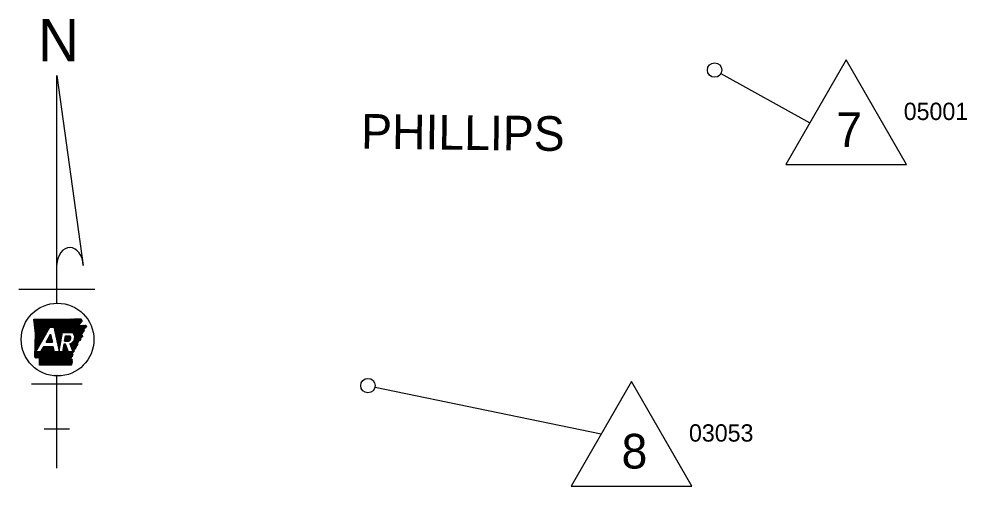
# Model space of a CAD drawing. Extents: x -31696 to 27919, y -8775 to 11152.
# Drawn here: x 10155 to 16721, y -2119 to 1115 of the extents above; entities that cross this region are included whole.
import ezdxf

# ---------------------------------------------------------------- set-up
doc = ezdxf.new("R2010")
doc.units = 0
for name, color, linetype in [('Level 2', 7, 'Continuous'), ('Level 48', 7, 'Continuous'), ('Level 50', 7, 'Continuous')]:
    doc.layers.add(name, color=color, linetype=linetype)

msp = doc.modelspace()

# ---------------------------------------------------------------- linework, layer by layer
at = {"layer": 'Level 48'}
for p, q in [((15883.2, 831.6), (15465.3, 107.7)), ((16301.2, 107.7), (15883.2, 831.6)), ((10418.4, 722.8), (10600.2, -591.3)), ((10418.4, -853), (10418.4, 722.8)), ((15016.1, 736.9), (15631.2, 395.8)), ((15465.3, 107.7), (16301.2, 107.7)), ((10155.2, -755.6), (10681.5, -755.6)), ((10258.7, -965.9), (10260.9, -963.7)), ((10259.5, -972.1), (10267.8, -963.7)), ((10260.3, -978.3), (10274.8, -963.7)), ((10261, -984.5), (10281.8, -963.8)), ((10261.8, -990.7), (10288.7, -963.8)), ((10262.6, -996.9), (10295.7, -963.8)), ((10263.3, -1003.1), (10302.6, -963.8)), ((10264.1, -1009.3), (10309.6, -963.8)), ((10264.9, -1015.5), (10316.6, -963.8)), ((10265.7, -1021.7), (10323.5, -963.8)), ((10266.4, -1027.9), (10330.5, -963.8)), ((10267.2, -1034), (10337.5, -963.8)), ((10268, -1040.2), (10344.4, -963.8)), ((10268.7, -1046.4), (10351.4, -963.8)), ((10269, -1115.9), (10421.2, -963.7)), ((10269.2, -1108.7), (10414.2, -963.7)), ((10269.4, -1101.5), (10407.2, -963.7)), ((10269.5, -1052.6), (10358.4, -963.8)), ((10269.7, -1094.2), (10400.2, -963.7)), ((10269.9, -1087), (10393.3, -963.7)), ((10270.2, -1079.8), (10386.3, -963.7)), ((10270.3, -1058.8), (10365.3, -963.8)), ((10270.4, -1072.6), (10379.3, -963.7)), ((10270.6, -1065.4), (10372.3, -963.8)), ((10372.4, -1019.4), (10428.2, -963.6)), ((10379.4, -1019.4), (10435.1, -963.6)), ((10386.3, -1019.4), (10442.2, -963.6)), ((10393.3, -1019.4), (10449.2, -963.5)), ((10397.6, -1022), (10456.3, -963.3)), ((10398.9, -1027.8), (10463.4, -963.2)), ((10400.1, -1033.5), (10470.5, -963.1)), ((10401.3, -1039.2), (10477.5, -963)), ((10402.6, -1045), (10484.6, -962.9)), ((10403.8, -1050.7), (10491.7, -962.8)), ((10405, -1056.4), (10498.8, -962.7)), ((10406.2, -1062.2), (10505.8, -962.6)), ((10407.5, -1067.9), (10512.9, -962.5)), ((10408.7, -1073.7), (10520, -962.4)), ((10409.9, -1079.4), (10527.1, -962.3)), ((10411.2, -1085.1), (10534.1, -962.1)), ((10412.4, -1090.9), (10541.2, -962)), ((10413.6, -1096.6), (10548.4, -961.8)), ((10462, -1055.2), (10555.5, -961.7)), ((10469, -1055.2), (10562.6, -961.5)), ((10475.9, -1055.2), (10569.8, -961.3)), ((10482.9, -1055.2), (10576.9, -961.2)), ((10489.9, -1055.2), (10584, -961)), ((10496.8, -1055.2), (10585.6, -966.4)), ((10503.8, -1055.2), (10588.9, -970)), ((10510.8, -1055.2), (10589.8, -976.1)), ((10268.5, -1130.3), (10353.6, -1045.1)), ((10268.7, -1123.1), (10362.7, -1029.1)), ((10271, -1191), (10368.2, -1019.4)), ((10368.2, -1019.4), (10397.1, -1019.4)), ((10517.7, -1055.2), (10573.9, -999)), ((10524.1, -1055.8), (10572.6, -1007.3)), ((10527.9, -1059), (10579.9, -1006.9)), ((10531.3, -1062.5), (10587.3, -1006.5)), ((10534.3, -1066.5), (10594.6, -1006.2)), ((10536.9, -1070.9), (10601.9, -1005.8)), ((10539, -1075.7), (10609.3, -1005.4)), ((10540.1, -1102.5), (10603.3, -1039.2)), ((10540.6, -1081.1), (10615.9, -1005.8)), ((10541.5, -1087.1), (10619.2, -1009.5)), ((10541.6, -1094), (10602.5, -1033.1)), ((10595.5, -1054), (10604.1, -1045.4)), ((10616.1, -1019.5), (10622.4, -1013.2)), ((10267.5, -1159.1), (10317.3, -1109.4)), ((10267.8, -1151.9), (10326.4, -1093.3)), ((10268, -1144.7), (10335.4, -1077.3)), ((10268.3, -1137.5), (10344.5, -1061.2)), ((10342.5, -1123.6), (10374.3, -1067.5)), ((10342.9, -1123.6), (10378.7, -1087.8)), ((10349.8, -1123.6), (10379.9, -1093.6)), ((10351.2, -1108.4), (10377.4, -1082.1)), ((10356.8, -1123.6), (10381.1, -1099.3)), ((10360.3, -1092.3), (10376.2, -1076.4)), ((10363.8, -1123.6), (10382.3, -1105.1)), ((10369.4, -1076.2), (10375, -1070.6)), ((10370.7, -1123.6), (10383.6, -1110.8)), ((10414.8, -1102.3), (10454.4, -1062.8)), ((10416.1, -1108.1), (10452.9, -1071.3)), ((10417.3, -1113.8), (10451.4, -1079.7)), ((10418.5, -1119.6), (10450, -1088.1)), ((10419.7, -1125.3), (10448.5, -1096.6)), ((10421, -1131), (10447, -1105)), ((10422.2, -1136.8), (10445.5, -1113.4)), ((10455.7, -1055.2), (10523.2, -1055.2)), ((10470.3, -1116), (10499.3, -1116)), ((10470.4, -1116), (10507, -1079.4)), ((10471.8, -1107.7), (10500.1, -1079.4)), ((10473.3, -1099.2), (10493.1, -1079.4)), ((10474.7, -1090.8), (10486.1, -1079.4)), ((10476.2, -1082.4), (10479.2, -1079.4)), ((10476.7, -1079.4), (10508.4, -1079.4)), ((10477.3, -1116), (10510.9, -1082.5)), ((10484.3, -1116), (10513.3, -1087.1)), ((10491.3, -1116), (10514.5, -1092.8)), ((10498.2, -1116), (10514, -1100.3)), ((10511.4, -1145.1), (10588.6, -1067.9)), ((10513.2, -1150.2), (10589.9, -1073.6)), ((10515.1, -1155.3), (10591.2, -1079.2)), ((10517, -1160.4), (10592.5, -1084.9)), ((10534.1, -1115.5), (10587.3, -1062.3)), ((10568.7, -1115.7), (10578.4, -1105.9)), ((10266.6, -1187.9), (10280.9, -1173.6)), ((10266.8, -1180.7), (10290, -1157.5)), ((10267.1, -1173.5), (10299.1, -1141.5)), ((10267.3, -1166.3), (10308.2, -1125.4)), ((10268.1, -1228.2), (10341.3, -1155)), ((10272.2, -1231), (10348.3, -1155)), ((10277.2, -1233), (10355.2, -1155)), ((10285.5, -1231.7), (10362.2, -1155)), ((10292.6, -1231.6), (10369.2, -1155)), ((10298, -1233.1), (10376.1, -1155)), ((10298.3, -1246.8), (10390.1, -1155)), ((10298.3, -1239.8), (10383.1, -1155)), ((10298.3, -1253.7), (10393.7, -1158.3)), ((10298.3, -1260.6), (10395, -1164)), ((10298.3, -1267.6), (10396.2, -1169.8)), ((10298.4, -1274.5), (10397.4, -1175.5)), ((10298.5, -1281.4), (10398.6, -1181.2)), ((10324.8, -1155), (10304.4, -1191)), ((10312.3, -1177), (10334.3, -1155)), ((10321.4, -1161), (10327.4, -1155)), ((10393, -1155), (10324.8, -1155)), ((10342.5, -1123.6), (10386.3, -1123.6)), ((10368, -1281.5), (10487.8, -1161.7)), ((10375, -1281.5), (10489.7, -1166.8)), ((10377.7, -1123.6), (10384.8, -1116.5)), ((10381.9, -1281.5), (10491.6, -1171.9)), ((10384.7, -1123.6), (10386, -1122.3)), ((10388.9, -1281.5), (10493.5, -1177)), ((10423.4, -1142.5), (10444.1, -1121.9)), ((10424.7, -1148.2), (10442.6, -1130.3)), ((10425.9, -1154), (10441.1, -1138.7)), ((10427.1, -1159.7), (10439.7, -1147.2)), ((10428.3, -1165.5), (10438.2, -1155.6)), ((10429.6, -1171.2), (10436.7, -1164)), ((10430.8, -1176.9), (10435.3, -1172.5)), ((10432, -1182.7), (10433.8, -1180.9)), ((10458.5, -1184.1), (10485.9, -1156.6)), ((10460, -1175.6), (10484.1, -1151.5)), ((10461.4, -1167.2), (10482.2, -1146.4)), ((10462.9, -1158.8), (10480.3, -1141.4)), ((10464.4, -1150.3), (10478.3, -1136.4)), ((10465.8, -1141.9), (10471.3, -1136.4)), ((10478.5, -1136.4), (10466.8, -1136.4)), ((10498.6, -1191), (10478.5, -1136.4)), ((10507, -1133.5), (10528.3, -1191)), ((10507.6, -1135), (10509.7, -1132.9)), ((10509.5, -1140.1), (10522.7, -1126.8)), ((10518.9, -1165.5), (10560.7, -1123.7)), ((10520.7, -1170.6), (10559.9, -1131.5)), ((10522.6, -1175.7), (10559.1, -1139.2)), ((10524.5, -1180.7), (10545.9, -1159.4)), ((10526.4, -1185.8), (10542.9, -1169.3)), ((10265.5, -1223.8), (10298.3, -1191)), ((10265.6, -1216.7), (10291.4, -1191)), ((10265.9, -1209.5), (10284.4, -1191)), ((10266.1, -1202.3), (10277.4, -1191)), ((10266.3, -1195.1), (10271.8, -1189.7)), ((10304.4, -1191), (10271, -1191)), ((10305.4, -1281.4), (10399.9, -1187)), ((10312.4, -1281.4), (10402.8, -1191)), ((10319.3, -1281.4), (10409.8, -1191)), ((10326.3, -1281.4), (10416.7, -1191)), ((10333.2, -1281.5), (10423.7, -1191)), ((10340.2, -1281.5), (10430.7, -1191)), ((10347.2, -1281.5), (10437.6, -1191)), ((10354.1, -1281.5), (10444.6, -1191)), ((10361.1, -1281.5), (10451.6, -1191)), ((10395.8, -1281.6), (10495.3, -1182)), ((10457.3, -1191), (10400.7, -1191)), ((10402.8, -1281.6), (10497.2, -1187.1)), ((10409.7, -1281.6), (10500.3, -1191)), ((10416.7, -1281.6), (10507.3, -1191)), ((10423.7, -1281.6), (10514.3, -1191)), ((10430.6, -1281.6), (10521.2, -1191)), ((10437.6, -1281.6), (10523.6, -1195.6)), ((10444.5, -1281.6), (10523.9, -1202.3)), ((10451.5, -1281.6), (10524.2, -1208.9)), ((10458.4, -1281.7), (10524.5, -1215.6)), ((10465.4, -1281.7), (10513.1, -1234)), ((10472.3, -1281.7), (10515.2, -1238.8)), ((10479.3, -1281.7), (10517.4, -1243.6)), ((10528.3, -1191), (10498.6, -1191)), ((10486.2, -1281.7), (10519.5, -1248.4)), ((10493.2, -1281.7), (10521.7, -1253.3)), ((10500.2, -1281.7), (10523.5, -1258.4)), ((10507.1, -1281.7), (10520.3, -1268.5)), ((10514.1, -1281.7), (10517.2, -1278.7)), ((10418.4, -1996.7), (10418.4, -1357.1)), ((10242.9, -1411.5), (10593.8, -1411.5)), ((12620.8, -1434.1), (14187.2, -1757.4)), ((14396.1, -1395.5), (13978.2, -2119.4)), ((14814.1, -2119.4), (14396.1, -1395.5)), ((10330.6, -1723.1), (10506.1, -1723.1)), ((13978.2, -2119.4), (14814.1, -2119.4))]:
    msp.add_line(p, q, dxfattribs=at)
for points in [[(10258.4, -963.8), (10354.5, -963.8), (10438.9, -963.6), (10538.4, -962.1), (10584.5, -961)], [(10258.4, -963.7), (10354.5, -963.8), (10438.9, -963.6), (10538.4, -962.1), (10584.5, -961)], [(10265.4, -1223.7), (10270.7, -1062.5), (10258.4, -963.7)], [(10269.1, -1113.1), (10270.7, -1062.5), (10258.4, -963.8)], [(10397.1, -1019.4), (10432.8, -1186.4), (10455.7, -1055.2)], [(10614.7, -1005.2), (10623, -1013.8), (10602.2, -1030.9), (10604.5, -1048.1), (10586.7, -1059.8), (10592.8, -1086.3), (10579.1, -1098.8), (10577.9, -1112.4), (10561.2, -1118.4), (10558.6, -1144), (10546.6, -1156.8), (10540.8, -1176.2), (10523.4, -1192.1), (10524.7, -1220.3), (10512.9, -1233.6), (10523.7, -1257.7), (10516.2, -1281.8)], [(10570.2, -1007.4), (10615.3, -1005.1)], [(10570.2, -1007.4), (10615.3, -1005.1)], [(10265.4, -1223.8), (10269.1, -1113.1)], [(10374.3, -1067.5), (10386.3, -1123.6)], [(10470.3, -1116), (10476.7, -1079.4)], [(10400.7, -1191), (10393, -1155)], [(10466.8, -1136.4), (10457.3, -1191)], [(10516.2, -1281.8), (10298.4, -1281.4), (10298.3, -1233.3)], [(10516.2, -1281.8), (10298.4, -1281.4), (10298.3, -1233.3)]]:
    msp.add_lwpolyline(points, dxfattribs=at)
for centre in [(14972.4, 761.2), (12571.8, -1424)]:
    msp.add_circle(centre, 50, dxfattribs=at)
for centre, major_axis, ratio, start_param, end_param in [((10509.2, -594.1), (-3.9, 126.3), 0.719778, 4.712385, 7.768526), ((10492.3, -1094.9), (-22.3, 0), 0.999987, 1.887169, 3.90762), ((10498.1, -1090.8), (-43.6, 0), 0.999987, 1.777838, 4.099264)]:
    msp.add_ellipse(centre, major_axis=major_axis, ratio=ratio, start_param=start_param, end_param=end_param, dxfattribs=at)
msp.add_ellipse((10422.5, -1105.1), major_axis=(252.1, 0), ratio=0.999976, dxfattribs=at)
for points in [[(10584.5, -961), (10584.8, -963.6), (10585.6, -965), (10585.7, -967.5), (10586.7, -968.6), (10588.5, -969.6), (10590, -971.3), (10590.4, -973.3), (10589.9, -975.4), (10589.8, -977.8), (10589.5, -979.8), (10589.1, -981.6), (10587.7, -983.1), (10586.4, -984.2), (10585.1, -985.4), (10584.2, -986.8), (10582.7, -988.1), (10581.1, -989.7), (10579.8, -990.9), (10578.6, -992.6), (10578, -994.4), (10576.7, -995.8), (10575.6, -997), (10574.2, -998.6), (10573.5, -1000.2), (10572.1, -1002), (10571.8, -1003.8), (10570.9, -1005.2), (10570.9, -1005.5)], [(10584.5, -961), (10584.8, -963.6), (10585.6, -965), (10585.7, -967.5), (10586.7, -968.6), (10588.5, -969.6), (10590, -971.3), (10590.4, -973.4), (10589.9, -975.4), (10589.8, -977.8), (10589.5, -979.8), (10589.2, -981.6), (10587.7, -983.1), (10586.4, -984.2), (10585.1, -985.4), (10584.2, -986.7), (10582.7, -988.2), (10581.1, -989.7), (10579.9, -991), (10578.7, -992.6), (10578.1, -994.5), (10576.7, -995.8), (10575.6, -997), (10574.2, -998.6), (10573.5, -1000.2), (10572.1, -1002), (10571.8, -1003.8), (10570.9, -1005.2), (10570.9, -1005.5)], [(10614.7, -1005.1), (10615.3, -1005.1), (10617.3, -1007.2), (10618.2, -1009), (10619.5, -1010), (10621, -1010.6), (10622.2, -1011.9), (10622.9, -1013.4), (10622.5, -1014.7), (10620.8, -1014.9), (10619, -1015.1), (10617.2, -1015.1), (10615.8, -1016.3), (10617.1, -1017.9), (10618.8, -1019.4), (10619.3, -1021), (10618.3, -1022.5), (10616.4, -1023.4), (10614.6, -1024.1), (10612.9, -1025.5), (10612.1, -1026.9), (10610.3, -1027.5), (10608.4, -1028), (10606.8, -1028.2), (10604.9, -1028.5), (10603, -1029.4), (10602.3, -1031), (10602.5, -1033.1), (10602.4, -1035.5), (10604.4, -1036.2), (10606.1, -1036.3), (10607.8, -1037.2), (10607.6, -1038.5), (10606.3, -1040.2), (10604.9, -1041.5), (10603.4, -1042.1), (10602, -1043.4), (10602.5, -1044.7), (10603.7, -1045.4), (10604.6, -1046.8), (10604.5, -1048.1), (10603.1, -1049), (10601.5, -1048.6), (10600.4, -1047.1), (10599.1, -1046.7), (10597.9, -1046.1), (10596.7, -1046.9), (10596.7, -1048.6), (10596.2, -1050.4), (10596.6, -1051.8), (10597.1, -1053.7), (10597, -1055.1), (10596.6, -1057.2), (10595.6, -1059.3), (10594.4, -1059.9), (10593.9, -1057.6), (10593.7, -1055.8), (10592.9, -1054.7), (10592, -1054.7), (10590.8, -1055.5), (10589.4, -1056.9), (10587.7, -1058.4), (10586.7, -1059.9), (10587.2, -1061.7), (10588.5, -1062.2), (10589.5, -1061.9), (10590.1, -1060.7), (10591, -1060.5), (10592, -1062.4)], [(10592, -1062.4), (10592.3, -1064), (10591.3, -1065.9), (10590.9, -1067.7), (10591, -1069.6), (10589.1, -1070.6), (10587.5, -1071.8), (10588.5, -1073.2), (10590.3, -1074.5), (10592, -1075.5), (10593.1, -1076.5), (10593.4, -1078.9), (10593.7, -1080.5), (10594.4, -1082.7), (10594.6, -1084.1), (10593.5, -1085.9), (10592.3, -1086.3), (10590.9, -1085.9), (10589.4, -1085.8), (10588.2, -1086.9), (10587.3, -1088.6), (10586.4, -1090.3), (10585.7, -1091.7), (10585, -1093.2), (10583.8, -1095), (10582.2, -1095.3), (10580.3, -1095.8), (10579.1, -1097.1), (10579.3, -1099.3), (10580.4, -1100.8), (10581.2, -1102.6), (10581.8, -1104.2), (10581.5, -1106.2), (10580.7, -1107.8), (10579.6, -1108.6), (10579.1, -1110.5), (10578.3, -1112), (10577.6, -1112.5), (10576.2, -1112.3), (10574.7, -1112), (10573.4, -1112.1), (10572.1, -1112.8), (10570.9, -1112.4), (10569.6, -1110.9), (10568.5, -1109.9), (10567.3, -1109.5), (10566, -1110.1), (10565.8, -1112.1), (10566.4, -1114.1), (10566.9, -1116.8), (10566.4, -1118.5), (10566.2, -1121.2)], [(10533.3, -1177.5), (10533.1, -1177.6), (10532.1, -1178.9), (10532.6, -1181), (10535, -1181.8), (10536, -1183.8), (10536.1, -1185.6), (10535.3, -1188.1), (10534.2, -1189.2), (10532.2, -1189.7), (10530.6, -1190), (10530.4, -1192.7), (10529.6, -1194.1), (10528.4, -1194.5), (10526.6, -1193.6), (10525.5, -1193.2), (10524.2, -1192.6), (10522.5, -1191.6), (10521.3, -1191.8), (10521.6, -1194.4), (10521.8, -1194.5), (10523.2, -1196.5), (10524.6, -1198), (10525.3, -1199.8)], [(10533.3, -1177.5), (10533.1, -1177.6), (10532.1, -1178.9), (10532.6, -1181), (10535, -1181.8), (10536, -1183.8), (10536.1, -1185.6), (10535.3, -1188.1), (10534.2, -1189.2), (10532.2, -1189.7), (10530.6, -1190), (10530.4, -1192.7), (10529.6, -1194.1), (10528.4, -1194.5), (10526.6, -1193.6), (10525.5, -1193.2), (10524.2, -1192.6), (10522.5, -1191.6), (10521.3, -1191.8), (10521.6, -1194.4), (10521.8, -1194.5), (10523.2, -1196.5), (10524.6, -1198), (10525.3, -1199.8)], [(10566.2, -1121.2), (10564.2, -1122.8), (10563.2, -1124.5), (10557.9, -1124), (10558.1, -1125.8), (10556.2, -1126.8), (10554.5, -1128), (10555.5, -1129.5), (10557.3, -1130.8), (10559, -1131.8), (10560.2, -1132.8), (10560.5, -1135.2), (10560.8, -1136.8), (10561.4, -1138.9), (10561.6, -1140.4), (10560.5, -1142.1), (10559.3, -1142.5), (10558, -1142.1), (10556.4, -1142), (10555.2, -1143.2), (10554.3, -1144.8), (10553.4, -1146.5), (10552.7, -1147.9), (10552, -1149.5), (10550.8, -1151.3), (10549.2, -1151.6), (10547.3, -1152), (10546.2, -1153.3), (10546.3, -1155.5), (10547.4, -1157), (10548.2, -1158.9), (10548.8, -1160.5), (10548.6, -1162.5), (10547.7, -1164), (10546.6, -1164.9), (10546.2, -1166.8), (10545.4, -1168.2), (10544.7, -1168.7), (10543.3, -1168.5), (10541.7, -1168.3), (10540.4, -1168.4), (10539.2, -1169), (10537.9, -1168.6), (10536.6, -1167.2), (10535.5, -1166.1), (10534.3, -1165.7), (10533, -1166.3), (10532.9, -1168.3), (10533.5, -1170.3), (10534, -1173.1), (10533.5, -1174.7), (10533.3, -1177.5)], [(10298.3, -1233.3), (10298.5, -1233.4), (10297.4, -1232.7), (10295.8, -1231.9), (10294.1, -1231.8), (10291.9, -1231.5), (10290.1, -1231.3), (10288.2, -1230), (10286.1, -1231.4), (10283.9, -1232.3), (10282.6, -1231.2), (10280.8, -1231.9), (10279.7, -1231.6), (10277.6, -1233), (10275.6, -1232.5), (10274.2, -1232.9), (10272.4, -1232.8), (10272, -1230.8), (10270.3, -1230.5), (10268.8, -1229.7), (10267.8, -1227.6), (10267.1, -1226), (10265.4, -1223.7)], [(10298.3, -1233.3), (10298.5, -1233.4), (10297.4, -1232.7), (10295.8, -1231.9), (10294.1, -1231.8), (10291.9, -1231.5), (10290, -1231.3), (10288.2, -1230), (10286.2, -1231.3), (10283.9, -1232.3), (10282.6, -1231.2), (10280.9, -1232), (10279.6, -1231.6), (10277.6, -1233), (10275.6, -1232.5), (10274.2, -1232.9), (10272.4, -1232.8), (10272.1, -1230.8), (10270.3, -1230.5), (10268.8, -1229.7), (10267.8, -1227.6), (10267.1, -1226), (10265.4, -1223.8)], [(10525.3, -1199.8), (10524.7, -1201.2), (10524, -1203.6), (10524.2, -1205.6), (10525.1, -1207.3), (10526.5, -1208.3), (10528.1, -1209.6), (10528, -1211.7), (10527.1, -1212.5), (10524.9, -1212), (10523.4, -1211.2), (10522, -1211.7), (10520.2, -1212.6), (10518.8, -1212.8), (10518.9, -1215.6), (10520.7, -1217.6), (10522.3, -1217.6), (10524.2, -1217.9), (10524.8, -1220), (10523.7, -1221.8), (10522, -1222.7), (10519.7, -1221.6), (10518.1, -1220.5), (10516.5, -1219.4), (10514.5, -1218.9), (10513.3, -1219.1), (10512.8, -1221.6), (10513.7, -1223.9), (10515.3, -1225.4), (10516.7, -1227.4), (10516.5, -1228.9), (10515.4, -1229.3), (10513.5, -1229.8), (10512.4, -1230.3), (10512.1, -1230.8), (10512.7, -1232.8), (10513.2, -1235), (10513.2, -1236.7), (10512.6, -1238.2), (10511.5, -1240.6), (10511.7, -1242.1), (10512.4, -1242.9), (10513.3, -1242.6), (10514.5, -1241.8), (10515.2, -1240.9), (10515.9, -1239.7), (10517.1, -1238.7), (10518.7, -1239.6), (10519, -1241.4), (10518.1, -1243), (10516.9, -1243.7), (10515.4, -1244.3), (10514.2, -1245.6), (10514.5, -1247.2), (10515.4, -1248), (10517.6, -1247.6), (10519.1, -1246.9), (10520, -1246.1), (10520.9, -1245.1), (10521.4, -1244), (10522.2, -1243), (10523.6, -1242.7), (10524.3, -1243.6), (10524, -1245.6), (10523.2, -1247.5), (10522, -1249.1), (10520.8, -1250.2), (10519.3, -1252.7), (10519.6, -1254.9), (10520.2, -1256.8), (10521, -1258.2), (10522.4, -1257.9), (10524, -1257.7), (10524.9, -1258.5), (10524.9, -1260.2), (10523.7, -1261.8), (10522.5, -1263.3), (10522, -1265.4), (10522.2, -1267), (10522.2, -1268.3), (10521.7, -1269.8), (10520.9, -1270.6), (10518.7, -1270.6), (10516.4, -1270.4), (10515.1, -1271.1), (10515.4, -1273.1), (10516.7, -1274.6), (10517.7, -1275.3), (10519, -1277), (10519.6, -1278.4), (10519.5, -1279.6), (10518.6, -1280.6), (10516.2, -1281.8)], [(10525.3, -1199.8), (10524.7, -1201.2), (10524, -1203.6), (10524.2, -1205.6), (10525.1, -1207.3), (10526.5, -1208.3), (10528.1, -1209.6), (10528, -1211.7), (10527.1, -1212.5), (10524.9, -1212), (10523.4, -1211.2), (10522, -1211.7), (10520.2, -1212.6), (10518.8, -1212.8), (10518.9, -1215.6), (10520.7, -1217.6), (10522.3, -1217.6), (10524.2, -1217.9), (10524.8, -1220), (10523.7, -1221.8), (10522, -1222.7), (10519.7, -1221.6), (10518.1, -1220.5), (10516.5, -1219.4), (10514.5, -1218.9), (10513.3, -1219.1), (10512.8, -1221.6), (10513.7, -1223.9), (10515.3, -1225.4), (10516.7, -1227.4), (10516.5, -1228.9), (10515.4, -1229.3), (10513.5, -1229.8), (10512.4, -1230.3), (10512.1, -1230.8), (10512.7, -1232.8), (10513.2, -1235), (10513.2, -1236.7), (10512.6, -1238.2), (10511.5, -1240.6), (10511.7, -1242.1), (10512.4, -1242.9), (10513.3, -1242.6), (10514.5, -1241.8), (10515.2, -1240.9), (10515.9, -1239.7), (10517.1, -1238.7), (10518.7, -1239.6), (10519, -1241.4), (10518.1, -1243), (10516.9, -1243.7), (10515.4, -1244.3), (10514.2, -1245.6), (10514.5, -1247.2), (10515.4, -1248), (10517.6, -1247.6), (10519.1, -1246.9), (10520, -1246.1), (10520.9, -1245.1), (10521.4, -1244), (10522.2, -1243), (10523.6, -1242.7), (10524.3, -1243.6), (10524, -1245.6), (10523.2, -1247.5), (10522, -1249.1), (10520.8, -1250.2), (10519.3, -1252.7), (10519.6, -1254.9), (10520.2, -1256.8), (10521, -1258.2), (10522.4, -1257.9), (10524, -1257.7), (10524.9, -1258.5), (10524.9, -1260.2), (10523.7, -1261.8), (10522.5, -1263.3), (10522, -1265.4), (10522.2, -1267), (10522.2, -1268.3), (10521.7, -1269.8), (10520.9, -1270.6), (10518.7, -1270.6), (10516.4, -1270.4), (10515.1, -1271.1), (10515.4, -1273.1), (10516.7, -1274.6), (10517.7, -1275.3), (10519, -1277), (10519.6, -1278.4), (10519.5, -1279.6), (10518.6, -1280.6), (10516.2, -1281.8)]]:
    msp.add_spline(points, degree=3, dxfattribs=at)

# ---------------------------------------------------------------- texts
at = {"layer": 'Level 2'}
msp.add_text('PHILLIPS', height=240, rotation=359.31794, dxfattribs=at).set_placement((12523.5, 217.6))
at = {"layer": 'Level 48'}
for s, height, p in [('N', 293.3, (10287.6, 822)), ('7', 240, (15815.2, 229)), ('STS 10-03-17', 7.288, (10398.3, -1355.1)), ('8', 240, (14328.1, -1998.1))]:
    msp.add_text(s, height=height, dxfattribs=at).set_placement(p)
at = {"layer": 'Level 50'}
for s, p in [('05001', (16282.2, 415.4)), ('03053', (14795.1, -1811.7))]:
    msp.add_text(s, height=120, dxfattribs=at).set_placement(p)

doc.saveas('drawing.dxf')
